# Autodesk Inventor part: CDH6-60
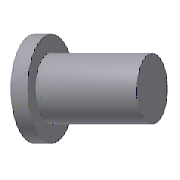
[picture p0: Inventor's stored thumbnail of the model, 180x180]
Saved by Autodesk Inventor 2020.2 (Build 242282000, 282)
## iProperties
Manager: www.cadconsulting.pl
Company: Fabian Stasiak CAD Consulting
Created: 2014-02
Part Number: CDH6-60
Material: SKD61
Description: Straight Core Pin
Document SubType Name: Modeling
Designer: F.Stasiak
Standard Revision: 1
Manufacturer: PUNCH
Language: pl-PL
Size Designation: 6-60
Categories: <MemberInstance><Categories><Category DisplayName="Forma wtryskowa" InternalName="349578f2-f4d4-4954-8c09-8e99297a61c0" Mnemonic="MOLD"><Category DisplayName="W
Mass: 1.61494 g
Surface Area: 11.4822 cm^2
Volume: 1.61494 cm^3
Density: 7.8 g/cm^3
Appearance: Aluminium - ciemne
Catalog Web Link: www.expertbooks.pl
IsCustomPart: 1
Author: F.Stasiak
Subject: Zbiór ćwiczeń. Autodesk Inventor 2020. Kurs Professional
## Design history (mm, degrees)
sketch "Sketch1"
  geometry: L1 (4.5, 0)-(4.5, 4); L2 (4.5, 4)-(3, 4); L3 (3, 4)-(3, 60); L4 (3, 60)-(0, 60); L5 (4.5, 0)-(0, 0); L6 (0, 0)-(0, 60); L7 (0, 60)-(0, -10) reference; 1 further point
  constraints: 14 end point, 2 horizontal, 1 coincident, 1 collinear, 1 parallel
  dimensions: "d2" = 4 distance of L1.start L1.end (= T_); "d19" = 60 distance between parallel lines of L4 L5 (= L); "d38" = 6 diameter of L3 L7 (= P); "d39" = 9 diameter of L1 L7 (= H_)
revolve "Revolution1" sketch "Sketch1" stored, may be unused: angle "d4" = 90 deg
fillet "Fillet1" dims "d36" = 0.3
workplane "Work Plane1"
sketch "Sketch2"
  geometry: 2 further points
  constraints: 1 vertical alignment
  dimensions: "d21" = 2 distance of point (0, -2) point (0, 0) (= 0.5 x T_)
hole "Anti_Rotary Hole" sketch "Sketch2" at (0, 0) diameter "d22" = 0.8 (= Anti_Rotary_D); stored, may be unused: countersink angle "d26" = 90 deg, drill point angle "d28" = 118 deg; dims "d23" = 6, "d24" = 4, "d25" = 2, "d27" = 1.2 (= 1.5 x Anti_Rotary_D)
sketch "Sketch3"
  geometry: L1 (-3.3, 3.059)-(-3.3, -3.059); A1 r 4.5 centre (0, 0) between (-3.3, 3.059) and (-3.3, -3.059) reference; 1 further point
  constraints: 2 end point, 2 point on circle, 1 vertical
  dimensions: "d29" = 3.3 distance from line of point (0, 0) L1 (= Anti_Rotary_P)
extrude "Anti_Rotary Plane" cut sketch "Sketch3" extent not by distance; stored distance "d30" = 10; taper "d31" = 0 deg
feature "Rzeźbienie1"
body "Solid1"
feature "Powierzchnia1"
body "Srf1"
other parameters: "H_" = 9 [user parameter; used in 1 equation term], "L" = 60 [user parameter; used in 1 equation term], "P" = 6 [user parameter; used in 1 equation term], "d7" = 0, "d8" = 0, "T_" = 4 [user parameter; used in 2 equation terms], "Anti_Rotary_P" = 3.3 [user parameter; used in 1 equation term], "Anti_Rotary_D" = 0.8 [user parameter; used in 2 equation terms], "d32" = 0, "d33" = 0, "d34" = 0, "d35" = 0, "IsARPlane" = 0 [user parameter], "IsARHole" = 0 [user parameter]
